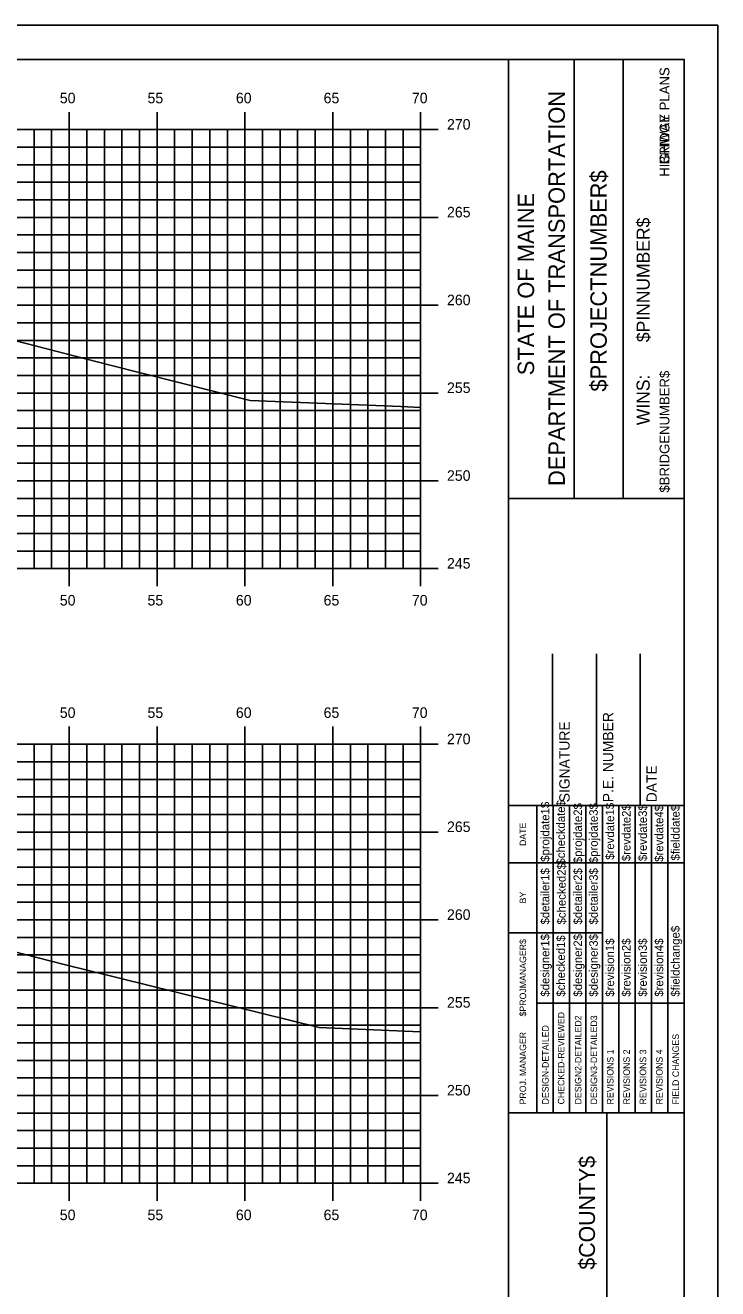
# Model space of a CAD drawing. Extents: x 1168600 to 1177589, y 610178 to 611246.
# Drawn here: x 1175676.4 to 1175715.8, y 610938.6 to 611010.5 of the extents above; entities that cross this region are included whole.
import ezdxf

# ---------------------------------------------------------------- set-up
doc = ezdxf.new("R2010")
doc.units = 0
for name, color, linetype in [('_Construction', 7, 'Continuous'), ('_Station Equation', 7, 'Continuous'), ('BORDER', 7, 'Continuous'), ('H_V ANNOTATION', 7, 'Continuous'), ('MAJOR', 7, 'Continuous'), ('MINOR', 7, 'Continuous')]:
    doc.layers.add(name, color=color, linetype=linetype)

msp = doc.modelspace()

# ---------------------------------------------------------------- linework, layer by layer
at = {"layer": '_Construction'}
for p, q in [((1175713.907, 611008.596), (1175553.907, 611008.596)), ((1175703.907, 610903.599), (1175703.907, 611008.599)), ((1175707.635, 610983.593), (1175707.635, 611008.593)), ((1175710.43, 610983.593), (1175710.43, 611008.593)), ((1175713.907, 610903.599), (1175713.907, 611008.599)), ((1175703.907, 610983.59), (1175713.907, 610983.59)), ((1175706.407, 610966.099), (1175706.407, 610974.747)), ((1175708.907, 610966.099), (1175708.907, 610974.747)), ((1175711.407, 610966.099), (1175711.407, 610974.747)), ((1175703.907, 610966.099), (1175713.907, 610966.099)), ((1175703.907, 610948.599), (1175713.907, 610948.599)), ((1175709.498, 610913.599), (1175709.498, 610948.599))]:
    msp.add_line(p, q, dxfattribs=at)
msp.add_lwpolyline([(1175545.813, 610900.537), (1175715.813, 610900.537), (1175715.813, 611010.537), (1175545.813, 611010.537)], close=True, dxfattribs=at)
for points in [[(1175705.521, 610962.849), (1175705.521, 610966.099)], [(1175706.454, 610948.602), (1175706.454, 610966.099)], [(1175707.386, 610966.099), (1175707.386, 610948.602)], [(1175708.317, 610948.602), (1175708.317, 610966.099)], [(1175709.249, 610948.602), (1175709.249, 610966.099)], [(1175710.181, 610948.602), (1175710.181, 610966.099)], [(1175711.112, 610948.602), (1175711.112, 610966.099)], [(1175712.044, 610948.602), (1175712.044, 610966.099)], [(1175712.976, 610948.602), (1175712.976, 610966.099)], [(1175705.522, 610948.602), (1175705.522, 610965.393)], [(1175703.907, 610962.849), (1175713.907, 610962.849)], [(1175703.907, 610958.849), (1175705.522, 610958.849)], [(1175705.521, 610958.849), (1175709.248, 610958.849)], [(1175705.521, 610954.849), (1175713.907, 610954.849)]]:
    msp.add_lwpolyline(points, dxfattribs=at)
at = {"layer": '_Station Equation'}
for points in [[(1175637.08, 610996.46), (1175640.207, 610996.5), (1175640.399, 610996.502), (1175641.26, 610996.501), (1175642.575, 610996.468), (1175645.221, 610996.394), (1175649.266, 610996.293), (1175650.235, 610996.268), (1175654.691, 610996.125), (1175655.249, 610996.109), (1175660.119, 610995.822), (1175660.263, 610995.814), (1175660.319, 610995.812), (1175662.202, 610995.772), (1175662.633, 610995.692), (1175665.26, 610995.293), (1175681.089, 610991.218), (1175689.212, 610989.175), (1175697.781, 610988.822), (1175698.906, 610988.773)], [(1175637.081, 610996.46), (1175640.207, 610996.5), (1175640.399, 610996.502), (1175641.26, 610996.501), (1175642.575, 610996.468), (1175645.221, 610996.394), (1175649.265, 610996.293), (1175650.235, 610996.268), (1175654.69, 610996.125), (1175655.249, 610996.109), (1175660.118, 610995.822), (1175660.263, 610995.814), (1175660.32, 610995.812), (1175662.202, 610995.772), (1175662.633, 610995.692), (1175665.26, 610995.293), (1175681.089, 610991.218), (1175689.212, 610989.175), (1175697.781, 610988.822), (1175698.906, 610988.773)], [(1175636.259, 610960.487), (1175639.258, 610960.542), (1175640.877, 610960.567), (1175644.277, 610960.618), (1175645.111, 610960.615), (1175645.415, 610960.614), (1175648.581, 610960.533), (1175649.296, 610960.513), (1175653.828, 610960.408), (1175654.315, 610960.397), (1175659.33, 610960.248), (1175659.334, 610960.248), (1175659.38, 610960.245), (1175664.353, 610959.954), (1175664.52, 610959.948), (1175666.413, 610959.876), (1175667.331, 610959.722), (1175669.953, 610959.283), (1175678.536, 610957.082), (1175693.131, 610953.47), (1175698.906, 610953.228)], [(1175636.259, 610960.487), (1175639.258, 610960.542), (1175640.876, 610960.567), (1175644.277, 610960.618), (1175645.111, 610960.615), (1175645.415, 610960.614), (1175648.581, 610960.533), (1175649.296, 610960.513), (1175653.829, 610960.408), (1175654.315, 610960.397), (1175659.331, 610960.248), (1175659.334, 610960.248), (1175659.371, 610960.246), (1175664.353, 610959.954), (1175664.52, 610959.948), (1175666.413, 610959.876), (1175666.759, 610959.818), (1175667.331, 610959.722), (1175669.953, 610959.283), (1175678.535, 610957.082), (1175693.131, 610953.47), (1175698.906, 610953.228)]]:
    msp.add_lwpolyline(points, dxfattribs=at)
at = {"layer": 'MAJOR'}
for p, q in [((1175678.906, 611005.598), (1175678.906, 611004.596)), ((1175683.906, 611005.598), (1175683.906, 611004.596)), ((1175688.906, 611005.598), (1175688.906, 611004.596)), ((1175693.906, 611005.598), (1175693.906, 611004.596)), ((1175698.906, 611005.598), (1175698.906, 611004.596)), ((1175558.906, 611004.596), (1175698.906, 611004.596)), ((1175558.906, 611004.596), (1175698.906, 611004.596)), ((1175678.906, 610979.596), (1175678.906, 611004.596)), ((1175683.906, 610979.596), (1175683.906, 611004.596)), ((1175688.906, 610979.596), (1175688.906, 611004.596)), ((1175693.906, 610979.596), (1175693.906, 611004.596)), ((1175699.908, 611004.596), (1175697.904, 611004.596)), ((1175698.906, 610979.596), (1175698.906, 611004.596)), ((1175698.906, 610979.596), (1175698.906, 611004.596)), ((1175558.906, 610999.596), (1175698.906, 610999.596)), ((1175699.908, 610999.596), (1175697.904, 610999.596)), ((1175558.906, 610994.596), (1175698.906, 610994.596)), ((1175699.908, 610994.596), (1175697.904, 610994.596)), ((1175558.906, 610989.596), (1175698.906, 610989.596)), ((1175699.908, 610989.596), (1175697.904, 610989.596)), ((1175558.906, 610984.596), (1175698.906, 610984.596)), ((1175699.908, 610984.596), (1175697.904, 610984.596)), ((1175558.906, 610979.596), (1175698.906, 610979.596)), ((1175558.906, 610979.596), (1175698.906, 610979.596)), ((1175678.906, 610978.594), (1175678.906, 610979.596)), ((1175683.906, 610978.594), (1175683.906, 610979.596)), ((1175688.906, 610978.594), (1175688.906, 610979.596)), ((1175693.906, 610978.594), (1175693.906, 610979.596)), ((1175699.908, 610979.596), (1175697.904, 610979.596)), ((1175698.906, 610978.594), (1175698.906, 610979.596)), ((1175678.906, 610970.598), (1175678.906, 610969.596)), ((1175683.906, 610970.598), (1175683.906, 610969.596)), ((1175688.906, 610970.598), (1175688.906, 610969.596)), ((1175693.906, 610970.598), (1175693.906, 610969.596)), ((1175698.906, 610970.598), (1175698.906, 610969.596)), ((1175558.906, 610969.596), (1175698.906, 610969.596)), ((1175558.906, 610969.596), (1175698.906, 610969.596)), ((1175678.906, 610944.596), (1175678.906, 610969.596)), ((1175683.906, 610944.596), (1175683.906, 610969.596)), ((1175688.906, 610944.596), (1175688.906, 610969.596)), ((1175693.906, 610944.596), (1175693.906, 610969.596)), ((1175699.908, 610969.596), (1175697.904, 610969.596)), ((1175698.906, 610944.596), (1175698.906, 610969.596)), ((1175698.906, 610944.596), (1175698.906, 610969.596)), ((1175558.906, 610964.596), (1175698.906, 610964.596)), ((1175699.908, 610964.596), (1175697.904, 610964.596)), ((1175558.906, 610959.596), (1175698.906, 610959.596)), ((1175699.908, 610959.596), (1175697.904, 610959.596)), ((1175558.906, 610954.596), (1175698.906, 610954.596)), ((1175699.908, 610954.596), (1175697.904, 610954.596)), ((1175558.906, 610949.596), (1175698.906, 610949.596)), ((1175699.908, 610949.596), (1175697.904, 610949.596)), ((1175558.906, 610944.596), (1175698.906, 610944.596)), ((1175558.906, 610944.596), (1175698.906, 610944.596)), ((1175678.906, 610943.594), (1175678.906, 610944.596)), ((1175683.906, 610943.594), (1175683.906, 610944.596)), ((1175688.906, 610943.594), (1175688.906, 610944.596)), ((1175693.906, 610943.594), (1175693.906, 610944.596)), ((1175699.908, 610944.596), (1175697.904, 610944.596)), ((1175698.906, 610943.594), (1175698.906, 610944.596))]:
    msp.add_line(p, q, dxfattribs=at)
at = {"layer": 'MINOR'}
for p, q in [((1175676.906, 610979.596), (1175676.906, 611004.596)), ((1175677.906, 610979.596), (1175677.906, 611004.596)), ((1175679.906, 610979.596), (1175679.906, 611004.596)), ((1175680.906, 610979.596), (1175680.906, 611004.596)), ((1175681.906, 610979.596), (1175681.906, 611004.596)), ((1175682.906, 610979.596), (1175682.906, 611004.596)), ((1175684.906, 610979.596), (1175684.906, 611004.596)), ((1175685.906, 610979.596), (1175685.906, 611004.596)), ((1175686.906, 610979.596), (1175686.906, 611004.596)), ((1175687.906, 610979.596), (1175687.906, 611004.596)), ((1175689.906, 610979.596), (1175689.906, 611004.596)), ((1175690.906, 610979.596), (1175690.906, 611004.596)), ((1175691.906, 610979.596), (1175691.906, 611004.596)), ((1175692.906, 610979.596), (1175692.906, 611004.596)), ((1175694.906, 610979.596), (1175694.906, 611004.596)), ((1175695.906, 610979.596), (1175695.906, 611004.596)), ((1175696.906, 610979.596), (1175696.906, 611004.596)), ((1175697.906, 610979.596), (1175697.906, 611004.596)), ((1175558.906, 611003.596), (1175698.906, 611003.596)), ((1175698.906, 611003.596), (1175697.904, 611003.596)), ((1175558.906, 611002.596), (1175698.906, 611002.596)), ((1175698.906, 611002.596), (1175697.904, 611002.596)), ((1175558.906, 611001.596), (1175698.906, 611001.596)), ((1175698.906, 611001.596), (1175697.904, 611001.596)), ((1175558.906, 611000.596), (1175698.906, 611000.596)), ((1175698.906, 611000.596), (1175697.904, 611000.596)), ((1175558.906, 610998.596), (1175698.906, 610998.596)), ((1175698.906, 610998.596), (1175697.904, 610998.596)), ((1175558.906, 610997.596), (1175698.906, 610997.596)), ((1175698.906, 610997.596), (1175697.904, 610997.596)), ((1175558.906, 610996.596), (1175698.906, 610996.596)), ((1175698.906, 610996.596), (1175697.904, 610996.596)), ((1175558.906, 610995.596), (1175698.906, 610995.596)), ((1175698.906, 610995.596), (1175697.904, 610995.596)), ((1175558.906, 610993.596), (1175698.906, 610993.596)), ((1175698.906, 610993.596), (1175697.904, 610993.596)), ((1175558.906, 610992.596), (1175698.906, 610992.596)), ((1175698.906, 610992.596), (1175697.904, 610992.596)), ((1175558.906, 610991.596), (1175698.906, 610991.596)), ((1175698.906, 610991.596), (1175697.904, 610991.596)), ((1175558.906, 610990.596), (1175698.906, 610990.596)), ((1175698.906, 610990.596), (1175697.904, 610990.596)), ((1175558.906, 610988.596), (1175698.906, 610988.596)), ((1175698.906, 610988.596), (1175697.904, 610988.596)), ((1175558.906, 610987.596), (1175698.906, 610987.596)), ((1175698.906, 610987.596), (1175697.904, 610987.596)), ((1175558.906, 610986.596), (1175698.906, 610986.596)), ((1175698.906, 610986.596), (1175697.904, 610986.596)), ((1175558.906, 610985.596), (1175698.906, 610985.596)), ((1175698.906, 610985.596), (1175697.904, 610985.596)), ((1175558.906, 610983.596), (1175698.906, 610983.596)), ((1175698.906, 610983.596), (1175697.904, 610983.596)), ((1175558.906, 610982.596), (1175698.906, 610982.596)), ((1175698.906, 610982.596), (1175697.904, 610982.596)), ((1175558.906, 610981.596), (1175698.906, 610981.596)), ((1175698.906, 610981.596), (1175697.904, 610981.596)), ((1175558.906, 610980.596), (1175698.906, 610980.596)), ((1175698.906, 610980.596), (1175697.904, 610980.596)), ((1175676.906, 610944.596), (1175676.906, 610969.596)), ((1175677.906, 610944.596), (1175677.906, 610969.596)), ((1175679.906, 610944.596), (1175679.906, 610969.596)), ((1175680.906, 610944.596), (1175680.906, 610969.596)), ((1175681.906, 610944.596), (1175681.906, 610969.596)), ((1175682.906, 610944.596), (1175682.906, 610969.596)), ((1175684.906, 610944.596), (1175684.906, 610969.596)), ((1175685.906, 610944.596), (1175685.906, 610969.596)), ((1175686.906, 610944.596), (1175686.906, 610969.596)), ((1175687.906, 610944.596), (1175687.906, 610969.596)), ((1175689.906, 610944.596), (1175689.906, 610969.596)), ((1175690.906, 610944.596), (1175690.906, 610969.596)), ((1175691.906, 610944.596), (1175691.906, 610969.596)), ((1175692.906, 610944.596), (1175692.906, 610969.596)), ((1175694.906, 610944.596), (1175694.906, 610969.596)), ((1175695.906, 610944.596), (1175695.906, 610969.596)), ((1175696.906, 610944.596), (1175696.906, 610969.596)), ((1175697.906, 610944.596), (1175697.906, 610969.596)), ((1175558.906, 610968.596), (1175698.906, 610968.596)), ((1175698.906, 610968.596), (1175697.904, 610968.596)), ((1175558.906, 610967.596), (1175698.906, 610967.596)), ((1175698.906, 610967.596), (1175697.904, 610967.596)), ((1175558.906, 610966.596), (1175698.906, 610966.596)), ((1175698.906, 610966.596), (1175697.904, 610966.596)), ((1175558.906, 610965.596), (1175698.906, 610965.596)), ((1175698.906, 610965.596), (1175697.904, 610965.596)), ((1175558.906, 610963.596), (1175698.906, 610963.596)), ((1175698.906, 610963.596), (1175697.904, 610963.596)), ((1175558.906, 610962.596), (1175698.906, 610962.596)), ((1175698.906, 610962.596), (1175697.904, 610962.596)), ((1175558.906, 610961.596), (1175698.906, 610961.596)), ((1175698.906, 610961.596), (1175697.904, 610961.596)), ((1175558.906, 610960.596), (1175698.906, 610960.596)), ((1175698.906, 610960.596), (1175697.904, 610960.596)), ((1175558.906, 610958.596), (1175698.906, 610958.596)), ((1175698.906, 610958.596), (1175697.904, 610958.596)), ((1175558.906, 610957.596), (1175698.906, 610957.596)), ((1175698.906, 610957.596), (1175697.904, 610957.596)), ((1175558.906, 610956.596), (1175698.906, 610956.596)), ((1175698.906, 610956.596), (1175697.904, 610956.596)), ((1175558.906, 610955.596), (1175698.906, 610955.596)), ((1175698.906, 610955.596), (1175697.904, 610955.596)), ((1175558.906, 610953.596), (1175698.906, 610953.596)), ((1175698.906, 610953.596), (1175697.904, 610953.596)), ((1175558.906, 610952.596), (1175698.906, 610952.596)), ((1175698.906, 610952.596), (1175697.904, 610952.596)), ((1175558.906, 610951.596), (1175698.906, 610951.596)), ((1175698.906, 610951.596), (1175697.904, 610951.596)), ((1175558.906, 610950.596), (1175698.906, 610950.596)), ((1175698.906, 610950.596), (1175697.904, 610950.596)), ((1175558.906, 610948.596), (1175698.906, 610948.596)), ((1175698.906, 610948.596), (1175697.904, 610948.596)), ((1175558.906, 610947.596), (1175698.906, 610947.596)), ((1175698.906, 610947.596), (1175697.904, 610947.596)), ((1175558.906, 610946.596), (1175698.906, 610946.596)), ((1175698.906, 610946.596), (1175697.904, 610946.596)), ((1175558.906, 610945.596), (1175698.906, 610945.596)), ((1175698.906, 610945.596), (1175697.904, 610945.596))]:
    msp.add_line(p, q, dxfattribs=at)

# ---------------------------------------------------------------- texts
at = {"layer": '_Construction'}
for s, height, p in [('BRIDGE PLANS', 0.55901, (1175713.065, 611002.62)), ('HIGHWAY PLANS', 0.55901, (1175713.065, 611001.911)), ('DEPARTMENT OF TRANSPORTATION', 0.93176, (1175707.113, 610984.302)), ('$PROJECTNUMBER$', 0.93176, (1175709.499, 610989.675)), ('STATE OF MAINE', 0.93176, (1175705.362, 610990.608)), ('$PINNUMBER$', 0.74527, (1175711.943, 610992.493)), ('$BRIDGENUMBER$', 0.55901, (1175713.065, 610983.926)), ('P.E. NUMBER', 0.59055, (1175709.867, 610966.291)), ('SIGNATURE', 0.5906, (1175707.387, 610966.291)), ('DATE', 0.5906, (1175712.348, 610966.291)), ('$projdate1$', 0.48455, (1175706.23, 610962.899)), ('$checkdate$', 0.48455, (1175707.124, 610962.742)), ('$projdate2$', 0.48455, (1175708.093, 610962.821)), ('$projdate3$', 0.48455, (1175708.987, 610962.821)), ('$revdate1$', 0.4845, (1175709.919, 610963.017)), ('$revdate2$', 0.4845, (1175710.851, 610962.939)), ('$revdate3$', 0.4845, (1175711.782, 610962.939)), ('$revdate4$', 0.4845, (1175712.714, 610962.899)), ('$fielddate$', 0.48455, (1175713.646, 610962.978)), ('DATE', 0.3714, (1175704.911, 610963.805)), ('$detailer1$', 0.48455, (1175706.23, 610959.334)), ('$checked2$', 0.4845, (1175707.161, 610959.334)), ('$detailer2$', 0.48455, (1175708.093, 610959.334)), ('$detailer3$', 0.48455, (1175708.987, 610959.334)), ('BY', 0.3714, (1175704.911, 610960.534)), ('$fieldchange$', 0.48455, (1175713.646, 610955.222)), ('$PROJMANAGER$', 0.37275, (1175704.911, 610954.094)), ('$designer1$', 0.48455, (1175706.23, 610955.222)), ('$checked1$', 0.4845, (1175707.124, 610955.222)), ('$designer2$', 0.48455, (1175708.093, 610955.222)), ('$designer3$', 0.48455, (1175708.987, 610955.222)), ('$revision1$', 0.48455, (1175709.919, 610955.222)), ('$revision2$', 0.48455, (1175710.851, 610955.222)), ('$revision3$', 0.48455, (1175711.782, 610955.222)), ('$revision4$', 0.48455, (1175712.714, 610955.222)), ('CHECKED-REVIEWED', 0.37275, (1175707.088, 610949.087)), ('DESIGN2-DETAILED2', 0.37275, (1175708.057, 610949.087)), ('DESIGN3-DETAILED3', 0.37275, (1175708.951, 610949.087)), ('PROJ. MANAGER', 0.37275, (1175704.911, 610949.087)), ('DESIGN-DETAILED', 0.37275, (1175706.193, 610949.087)), ('FIELD CHANGES', 0.37275, (1175713.609, 610949.087)), ('REVISIONS 1', 0.37275, (1175709.883, 610949.087)), ('REVISIONS 2', 0.37275, (1175710.814, 610949.087)), ('REVISIONS 3', 0.37275, (1175711.746, 610949.087)), ('REVISIONS 4', 0.37275, (1175712.678, 610949.087)), ('$COUNTY$', 0.9072, (1175708.827, 610939.678))]:
    msp.add_text(s, height=height, rotation=90, dxfattribs=at).set_placement(p)
at = {"layer": 'BORDER'}
msp.add_text('WINS:', height=0.7453, rotation=90, dxfattribs=at).set_placement((1175711.941, 610987.764))
at = {"layer": 'H_V ANNOTATION'}
for s, p in [('50', (1175678.371, 611006.096)), ('55', (1175683.363, 611006.096)), ('60', (1175688.393, 611006.096)), ('65', (1175693.385, 611006.096)), ('70', (1175698.408, 611006.096)), ('270', (1175700.406, 611004.596)), ('265', (1175700.406, 610999.596)), ('260', (1175700.406, 610994.596)), ('255', (1175700.406, 610989.596)), ('250', (1175700.406, 610984.596)), ('245', (1175700.406, 610979.596)), ('50', (1175678.371, 610977.496)), ('55', (1175683.363, 610977.496)), ('60', (1175688.393, 610977.496)), ('65', (1175693.385, 610977.496)), ('70', (1175698.408, 610977.496)), ('50', (1175678.371, 610971.096)), ('55', (1175683.363, 610971.096)), ('60', (1175688.393, 610971.096)), ('65', (1175693.385, 610971.096)), ('70', (1175698.408, 610971.096)), ('270', (1175700.406, 610969.596)), ('265', (1175700.406, 610964.596)), ('260', (1175700.406, 610959.596)), ('255', (1175700.406, 610954.596)), ('250', (1175700.406, 610949.596)), ('245', (1175700.406, 610944.596)), ('50', (1175678.371, 610942.496)), ('55', (1175683.363, 610942.496)), ('60', (1175688.393, 610942.496)), ('65', (1175693.385, 610942.496)), ('70', (1175698.408, 610942.496))]:
    msp.add_text(s, height=0.6, dxfattribs=at).set_placement(p)

doc.saveas('drawing.dxf')
